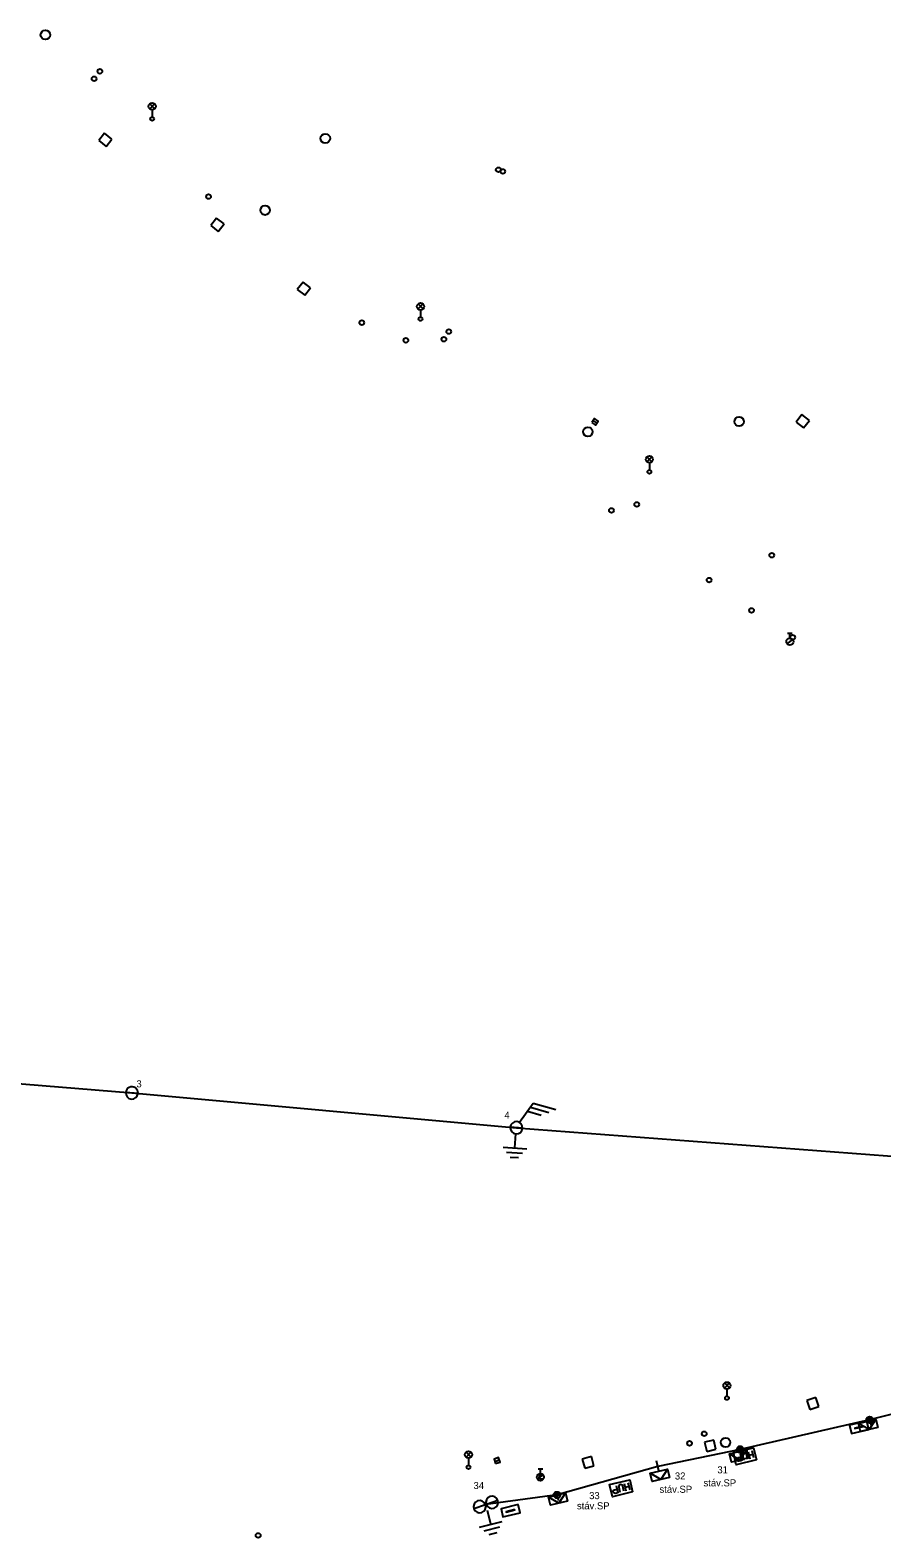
# Model space of a CAD drawing. Extents: x -544660 to -541587, y -1198996 to -1195866.
# Drawn here: x -543113 to -543022.8, y -1198229.2 to -1198069.5 of the extents above; entities that cross this region are included whole.
import ezdxf

# ---------------------------------------------------------------- set-up
doc = ezdxf.new("R2010")
doc.units = 0
for name, color, linetype in [('CIZÍ_NADZEM', 7, 'Continuous'), ('ELE_EON', 7, 'Continuous'), ('ELE_EON_POPIS', 7, 'Continuous')]:
    doc.layers.add(name, color=color, linetype=linetype)

msp = doc.modelspace()

# ---------------------------------------------------------------- linework, layer by layer
at = {"layer": 'CIZÍ_NADZEM'}
for p, q in [((-543100.3, -1198077.82), (-543099.78, -1198077.29)), ((-543099.77, -1198077.81), (-543100.3, -1198077.29)), ((-543100.04, -1198077.93), (-543100.04, -1198078.68)), ((-543105.08, -1198080.39), (-543105.7, -1198081.17)), ((-543104.3, -1198081.01), (-543105.08, -1198080.39)), ((-543105.7, -1198081.17), (-543104.92, -1198081.79)), ((-543104.92, -1198081.79), (-543104.3, -1198081.01)), ((-543093.22, -1198089.39), (-543093.83, -1198090.18)), ((-543093.83, -1198090.18), (-543093.04, -1198090.79)), ((-543092.43, -1198090), (-543093.22, -1198089.39)), ((-543093.04, -1198090.79), (-543092.43, -1198090)), ((-543084.07, -1198096.16), (-543084.68, -1198096.95)), ((-543083.28, -1198096.77), (-543084.07, -1198096.16)), ((-543084.68, -1198096.95), (-543083.89, -1198097.56)), ((-543083.89, -1198097.56), (-543083.28, -1198096.77)), ((-543071.89, -1198099.01), (-543071.37, -1198098.48)), ((-543071.36, -1198099.01), (-543071.89, -1198098.48)), ((-543071.63, -1198099.12), (-543071.63, -1198099.87)), ((-543053.37, -1198110.82), (-543052.95, -1198111.1)), ((-543031.25, -1198110.2), (-543031.86, -1198110.99)), ((-543030.46, -1198110.81), (-543031.25, -1198110.2)), ((-543031.07, -1198111.6), (-543030.46, -1198110.81)), ((-543031.86, -1198110.99), (-543031.07, -1198111.6)), ((-543047.66, -1198115.2), (-543047.14, -1198114.67)), ((-543047.13, -1198115.2), (-543047.66, -1198114.67)), ((-543047.4, -1198115.31), (-543047.4, -1198116.06)), ((-543032.81, -1198134.47), (-543032.22, -1198134.01)), ((-543032.77, -1198133.36), (-543032.27, -1198133.36)), ((-543032.52, -1198133.86), (-543032.52, -1198133.36)), ((-543039.45, -1198213.29), (-543038.93, -1198212.76)), ((-543038.92, -1198213.28), (-543039.45, -1198212.76)), ((-543039.19, -1198213.4), (-543039.19, -1198214.15)), ((-543029.77, -1198214.29), (-543030.72, -1198214.6)), ((-543030.72, -1198214.6), (-543030.41, -1198215.55)), ((-543029.46, -1198215.24), (-543029.77, -1198214.29)), ((-543030.41, -1198215.55), (-543029.46, -1198215.24)), ((-543040.58, -1198218.81), (-543041.55, -1198219.04)), ((-543041.55, -1198219.04), (-543041.32, -1198220.01)), ((-543040.35, -1198219.78), (-543040.58, -1198218.81)), ((-543066.81, -1198220.62), (-543066.29, -1198220.09)), ((-543066.28, -1198220.61), (-543066.81, -1198220.09)), ((-543066.55, -1198220.73), (-543066.55, -1198221.48)), ((-543063.76, -1198221.06), (-543063.28, -1198220.9)), ((-543053.54, -1198220.56), (-543054.5, -1198220.82)), ((-543054.5, -1198220.82), (-543054.24, -1198221.78)), ((-543053.28, -1198221.52), (-543053.54, -1198220.56)), ((-543041.32, -1198220.01), (-543040.35, -1198219.78)), ((-543059.23, -1198222.96), (-543058.64, -1198222.5)), ((-543059.19, -1198221.85), (-543058.69, -1198221.85)), ((-543058.94, -1198222.35), (-543058.94, -1198221.85)), ((-543054.24, -1198221.78), (-543053.28, -1198221.52))]:
    msp.add_line(p, q, dxfattribs=at)
for points in [[(-543053.51, -1198111.03), (-543053.1, -1198111.31), (-543052.81, -1198110.9), (-543053.22, -1198110.61)], [(-543063.68, -1198221.3), (-543063.2, -1198221.14), (-543063.36, -1198220.66), (-543063.84, -1198220.82)]]:
    msp.add_lwpolyline(points, close=True, dxfattribs=at)
for points in [[(-543036.07, -1198220.9), (-543038.21, -1198221.41), (-543038.51, -1198220.12), (-543036.37, -1198219.62), (-543036.07, -1198220.9)], [(-543037.63, -1198220.99), (-543037.91, -1198221.05), (-543038, -1198221.04), (-543038.04, -1198221.01), (-543038.09, -1198220.95), (-543038.12, -1198220.84), (-543038.1, -1198220.76), (-543038.08, -1198220.72), (-543038, -1198220.66), (-543037.72, -1198220.6)], [(-543037.8, -1198220.24), (-543037.63, -1198220.99)], [(-543036.99, -1198220.84), (-543037.11, -1198220.3), (-543037.17, -1198220.2), (-543037.25, -1198220.15), (-543037.35, -1198220.13), (-543037.41, -1198220.15), (-543037.49, -1198220.2), (-543037.54, -1198220.29), (-543037.54, -1198220.4), (-543037.42, -1198220.94)], [(-543036.95, -1198220.04), (-543036.77, -1198220.79)], [(-543036.43, -1198220.33), (-543036.86, -1198220.43)], [(-543036.34, -1198220.68), (-543036.52, -1198219.94)], [(-543049.17, -1198224.29), (-543051.31, -1198224.8), (-543051.62, -1198223.52), (-543049.48, -1198223), (-543049.17, -1198224.29)], [(-543050.73, -1198224.38), (-543051.01, -1198224.45), (-543051.11, -1198224.43), (-543051.15, -1198224.4), (-543051.2, -1198224.34), (-543051.22, -1198224.23), (-543051.21, -1198224.16), (-543051.19, -1198224.11), (-543051.1, -1198224.06), (-543050.83, -1198223.99)], [(-543050.91, -1198223.63), (-543050.73, -1198224.38)], [(-543050.09, -1198224.22), (-543050.22, -1198223.69), (-543050.28, -1198223.59), (-543050.36, -1198223.53), (-543050.46, -1198223.52), (-543050.52, -1198223.54), (-543050.6, -1198223.59), (-543050.65, -1198223.68), (-543050.65, -1198223.79), (-543050.52, -1198224.33)], [(-543050.06, -1198223.42), (-543049.88, -1198224.17)], [(-543049.53, -1198223.72), (-543049.96, -1198223.82)], [(-543049.45, -1198224.07), (-543049.63, -1198223.32)]]:
    msp.add_lwpolyline(points, dxfattribs=at)
for centre, radius in [((-543111.35, -1198069.98), 0.5), ((-543105.57, -1198073.84), 0.25), ((-543106.19, -1198074.63), 0.25), ((-543100.04, -1198077.55), 0.375), ((-543100.04, -1198078.88), 0.2), ((-543081.71, -1198080.95), 0.5), ((-543063.39, -1198084.27), 0.25), ((-543062.92, -1198084.44), 0.25), ((-543094.07, -1198087.11), 0.25), ((-543088.08, -1198088.56), 0.5), ((-543071.63, -1198098.75), 0.375), ((-543077.85, -1198100.46), 0.25), ((-543071.63, -1198100.07), 0.2), ((-543068.64, -1198101.41), 0.25), ((-543073.18, -1198102.33), 0.25), ((-543069.16, -1198102.21), 0.25), ((-543037.9, -1198110.93), 0.5), ((-543053.91, -1198112.02), 0.5), ((-543047.4, -1198114.94), 0.375), ((-543047.4, -1198116.26), 0.2), ((-543051.42, -1198120.35), 0.25), ((-543048.73, -1198119.71), 0.25), ((-543034.44, -1198125.09), 0.25), ((-543041.08, -1198127.72), 0.25), ((-543036.58, -1198130.93), 0.25), ((-543032.52, -1198134.24), 0.375), ((-543032.23, -1198133.78), 0.25), ((-543039.19, -1198213.03), 0.375), ((-543039.19, -1198214.35), 0.2), ((-543041.59, -1198218.14), 0.25), ((-543043.15, -1198219.15), 0.25), ((-543039.34, -1198219.06), 0.5), ((-543066.55, -1198220.35), 0.375), ((-543066.55, -1198221.68), 0.2), ((-543058.94, -1198222.73), 0.375), ((-543058.81, -1198222.71), 0.25), ((-543088.82, -1198228.91), 0.25)]:
    msp.add_circle(centre, radius, dxfattribs=at)
at = {"layer": 'ELE_EON'}
for p, q in [((-543101.54, -1198182.1), (-543102.84, -1198181.98)), ((-543061.16, -1198185.14), (-543059.69, -1198183.11)), ((-543060.3, -1198183.98), (-543058.86, -1198184.39)), ((-543059.97, -1198183.55), (-543058.05, -1198184.11)), ((-543059.69, -1198183.11), (-543057.29, -1198183.81)), ((-543060.83, -1198185.77), (-543062.13, -1198185.67)), ((-543061.63, -1198187.86), (-543061.53, -1198186.37)), ((-543062.88, -1198187.78), (-543060.39, -1198187.95)), ((-543062.52, -1198188.3), (-543060.82, -1198188.42)), ((-543062.15, -1198188.83), (-543061.25, -1198188.89)), ((-543024, -1198216.99), (-543023.94, -1198217.23)), ((-543046.37, -1198222.22), (-543046.65, -1198221)), ((-543037.7, -1198220.13), (-543037.64, -1198220.37)), ((-543064.76, -1198225.66), (-543065.98, -1198226.09)), ((-543063.44, -1198225.19), (-543064.66, -1198225.62)), ((-543057.1, -1198224.96), (-543057.04, -1198225.2)), ((-543065.39, -1198228.03), (-543062.97, -1198227.42)), ((-543064.18, -1198227.72), (-543064.55, -1198226.27)), ((-543064.88, -1198228.42), (-543063.23, -1198228)), ((-543064.37, -1198228.8), (-543063.5, -1198228.58))]:
    msp.add_line(p, q, dxfattribs=at)
for points in [[(-543301.15, -1198165.16), (-543229.58, -1198170.88), (-543163.5, -1198177), (-543102.19, -1198182.04), (-543061.48, -1198185.72), (-542997.89, -1198190.52), (-542988.09, -1198186.26), (-542975.57, -1198180.94)], [(-542906.27, -1198186.64), (-542928.49, -1198192.12), (-542956, -1198198.44), (-542981.94, -1198206.13), (-543006.12, -1198212.41), (-543012.46, -1198213.75), (-543024.08, -1198216.65), (-543037.78, -1198219.79), (-543046.51, -1198221.61), (-543057.18, -1198224.62), (-543064.71, -1198225.64)], [(-543023.44, -1198216.6), (-543024.14, -1198217.7), (-543025.26, -1198217.04)], [(-543037.11, -1198219.82), (-543037.81, -1198220.92), (-543038.93, -1198220.26)], [(-543045.48, -1198221.88), (-543046.18, -1198222.98), (-543047.3, -1198222.32)], [(-543056.27, -1198224.4), (-543056.97, -1198225.49), (-543058.09, -1198224.84)]]:
    msp.add_lwpolyline(points, dxfattribs=at)
for points in [[(-543024.38, -1198216.8), (-543026.2, -1198217.24), (-543025.99, -1198218.11), (-543024.17, -1198217.68)], [(-543024.73, -1198217.33), (-543025.65, -1198217.55), (-543025.64, -1198217.59), (-543024.72, -1198217.37)], [(-543023.23, -1198217.48), (-543025.05, -1198217.91), (-543025.26, -1198217.04), (-543023.44, -1198216.6)], [(-543036.9, -1198220.7), (-543038.72, -1198221.13), (-543038.93, -1198220.26), (-543037.11, -1198219.82)], [(-543045.27, -1198222.76), (-543047.1, -1198223.19), (-543047.3, -1198222.32), (-543045.48, -1198221.88)], [(-543061.29, -1198225.64), (-543063.11, -1198226.08), (-543062.9, -1198226.95), (-543061.08, -1198226.52)], [(-543056.06, -1198225.28), (-543057.88, -1198225.71), (-543058.09, -1198224.84), (-543056.27, -1198224.4)], [(-543061.64, -1198226.17), (-543062.55, -1198226.39), (-543062.55, -1198226.43), (-543061.63, -1198226.21)]]:
    msp.add_lwpolyline(points, close=True, dxfattribs=at)
for centre, radius in [((-543024.08, -1198216.65), 0.35), ((-543024.08, -1198216.65), 0.175), ((-543037.78, -1198219.79), 0.35), ((-543037.78, -1198219.79), 0.175), ((-543057.18, -1198224.62), 0.35), ((-543057.18, -1198224.62), 0.175)]:
    msp.add_circle(centre, radius, dxfattribs=at)
for centre, start, end in [((-543102.19, -1198182.04), 354.8348, 174.8348), ((-543102.19, -1198182.04), 174.8348, 354.8348), ((-543061.48, -1198185.72), 355.6833, 175.6833), ((-543061.48, -1198185.72), 175.6833, 355.6833), ((-543065.37, -1198225.87), 19.44, 199.44), ((-543065.37, -1198225.87), 199.44, 19.44), ((-543064.05, -1198225.41), 19.44, 199.44), ((-543064.05, -1198225.41), 199.44, 19.44)]:
    msp.add_arc(centre, 0.65, start, end, dxfattribs=at)

# ---------------------------------------------------------------- texts
at = {"layer": 'ELE_EON_POPIS'}
for s, p in [('3', (-543101.71, -1198181.45)), ('4', (-543062.75, -1198184.77)), ('32', (-543044.7, -1198222.98)), ('31', (-543040.2, -1198222.33)), ('34', (-543066.02, -1198223.99)), ('33', (-543053.78, -1198225.06)), ('stáv.SP', (-543046.33, -1198224.39)), ('stáv.SP', (-543041.67, -1198223.71)), ('stáv.SP', (-543055.07, -1198226.14))]:
    msp.add_text(s, height=0.75, dxfattribs=at).set_placement(p)

doc.saveas('drawing.dxf')
